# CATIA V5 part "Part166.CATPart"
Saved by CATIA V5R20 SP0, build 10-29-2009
Part number: FA 126700-3
Revision: ANY
Definition: UNKNOWN
Nomenclature: FA 126700-3
Source: Unknown
Bounding box of the stored display mesh (mm): x -3.264 to 3.264, y -2.475 to 2.475, z -3 to 3
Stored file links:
  C:\Users\Utente\Desktop\IO LAVORO\3D X SITO CF\CUMSA\3D files FA\FA 126700\Part166.CATPart
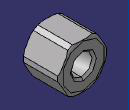
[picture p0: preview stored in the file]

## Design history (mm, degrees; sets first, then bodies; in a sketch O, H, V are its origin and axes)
Body1 "Chaflán4" (main body)
  Solid1: solid without history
